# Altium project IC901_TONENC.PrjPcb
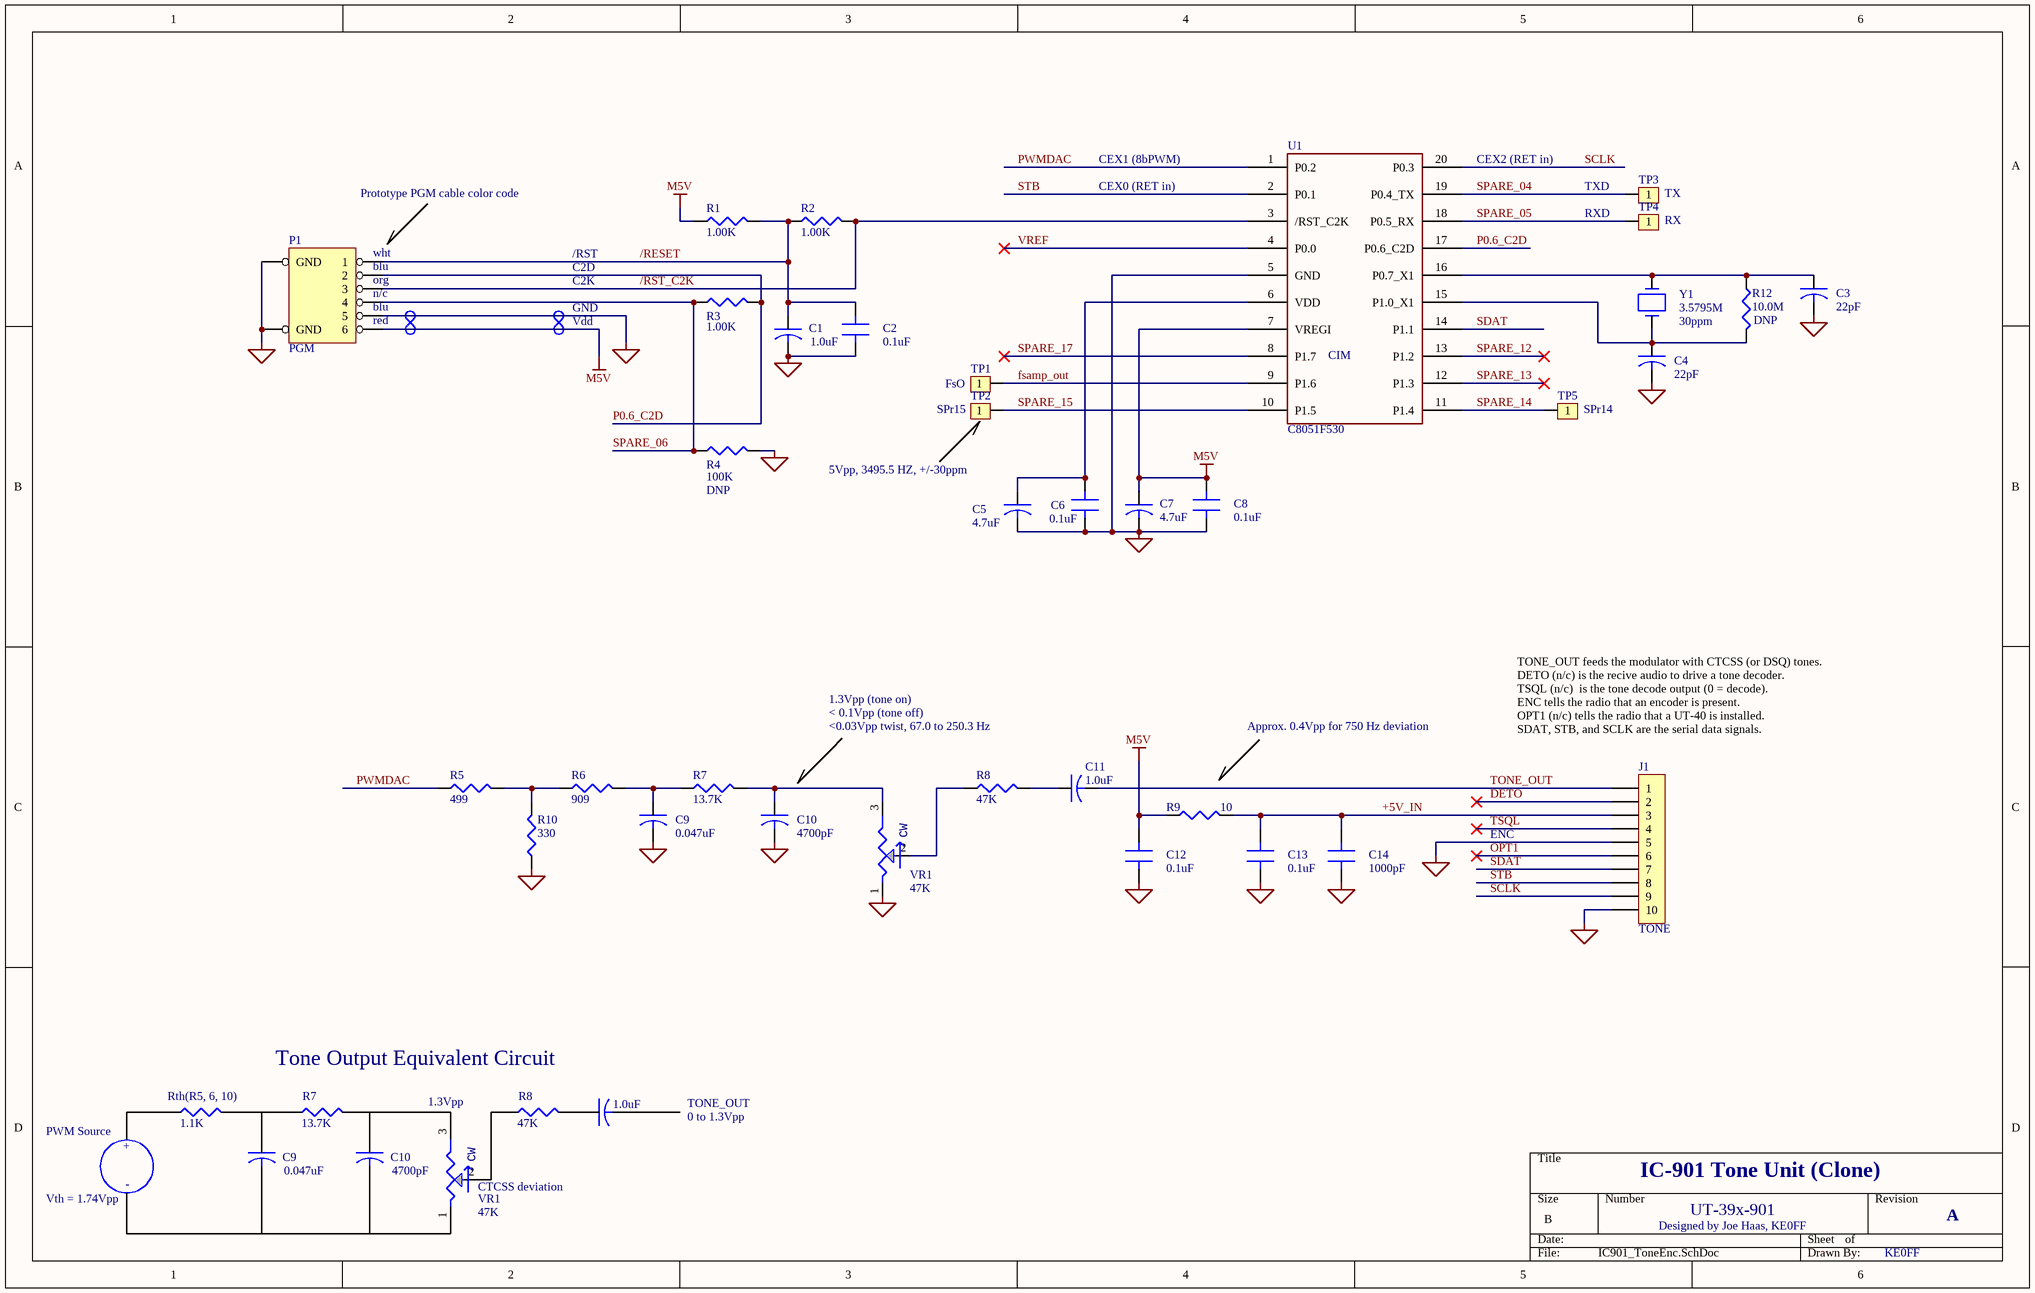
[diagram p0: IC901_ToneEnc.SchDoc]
1 sheet, 42 parts. Net scope: global (net labels, ports and power ports of the same name join across sheets).
Board file: IC901_ToneEnc.PcbDoc

## Sheet IC901_ToneEnc.SchDoc
size B; SheetNumber: 1; SheetTotal: 1

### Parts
C1  1.0uF  [0805]
C2  0.1uF  [0402]
C3  22pF  [0402]
C4  22pF  [0402]
C5  4.7uF  [0805]
C6  0.1uF  [0402]
C7  4.7uF  [0805]
C8  0.1uF  [0402]
C9  0.047uF  [1206]
C10  4700pF  [0805]
C11  1.0uF  [0805]
C12  0.1uF  [0402]
C13  0.1uF  [0402]
C14  1000pF  [0402]
Ce1  0.047uF  [1206]
Ce2  4700pF  [0805]
Ce3  1.0uF  [0805]  (graphical)
J1  TONE  [MOLEX_1.5mm_SMD_10POS]
P1  PGM  [CON_1.25MM_6P]
R1  1.00K  [0402]
R2  1.00K  [0402]
R3  1.00K  [0402]
R4  100K  [0402]
R5  499  [0402]
R6  909  [0402]
R7  13.7K  [0402]
R8  47K  [0402]
R9  10  [1206]
R10  330  [0402]
R12  10.0M  [0402]
Re1  1.1K  [0402]  (graphical)
Re2  13.7K  [0402]  (graphical)
Re3  47K  [0402]  (graphical)
TP1  FsO  [TP-SMD-20x50-SQ]  (no BOM)
TP2  SPr15  [TP-SMD-20x50-SQ]  (no BOM)
TP3  TX  [TP-SMD-20x50-SQ]  (no BOM)
TP4  RX  [TP-SMD-20x50-SQ]  (no BOM)
TP5  SPr14  [TP-SMD-20x50-SQ]  (no BOM)
U1  C8051F530  [TSSOP-20]
VR1  47K  [POT_3313]
VRe1  47K  [POT_3313]  (graphical)
Y1  3.5795M  Stability: 30ppm  [XTAL_AT49_SMD]

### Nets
GND: C1.2 C2.2 C3.2 C4.2 C5.2 C6.2 C7.2 C8.2 C9.2 C10.2 C12.2 C13.2 C14.2 J1.5 J1.10 P1.5 P1.7(GND) P1.8(GND) R4.1 R10.2 U1.5(GND) VR1.1(A)
M5V: C7.1 C8.1 C12.1 P1.6 R1.2 R9.2 U1.7(VREGI)
+5V_IN: C13.1 C14.1 J1.3 R9.1
/RESET: C1.1 C2.1 P1.1 R1.1 R2.2
/RST_C2K: P1.3 R2.1 U1.3(/RST_C2K)
DETO: J1.2
fsamp_out: TP1.1 U1.9(P1.6)
OPT1: J1.6
P0.6_C2D: P1.2 R3.1 U1.17(P0.6_C2D)
PWMDAC: R5.2 U1.1(P0.2)
SCLK: J1.9 U1.20(P0.3)
SDAT: J1.7 U1.14(P1.1)
SPARE_04: TP3.1 U1.19(P0.4_TX)
SPARE_05: TP4.1 U1.18(P0.5_RX)
SPARE_06: P1.4 R3.2 R4.2
SPARE_12: U1.13(P1.2)
SPARE_13: U1.12(P1.3)
SPARE_14: TP5.1 U1.11(P1.4)
SPARE_15: TP2.1 U1.10(P1.5)
SPARE_17: U1.8(P1.7)
STB: J1.8 U1.2(P0.1)
TONE_OUT: C11.2 J1.1
TSQL: J1.4
VREF: U1.4(P0.0)
NetC3_1: C3.1 R12.1 U1.16(P0.7_X1) Y1.2
NetC4_1: C4.1 R12.2 U1.15(P1.0_X1) Y1.1
NetC5_1: C5.1 C6.1 U1.6(VDD)
NetC9_1: C9.1 R6.1 R7.2
NetC10_1: C10.1 R7.1 VR1.3(B)
NetC11_1: C11.1 R8.1
NetR5_1: R5.1 R6.2 R10.1
NetR8_2: R8.2 VR1.2(WIPER)

Not connected (* = marked no-connect by the designer): Ce1 1 2; Ce2 1 2; Ce3 1 2; Re1 1 2; Re2 1 2; Re3 1 2; VRe1 1(A) 2(WIPER) 3(B)

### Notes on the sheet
- CEX1 (8bPWM)
- CEX2 (RET in)
- Prototype PGM cable color code
- CEX0 (RET in)
- TXD
- RXD
- (near P1) wht
- (near P1) blu
- (near P1) org
- (near P1) n/c
- /RST
- C2D
- C2K
- (near P1) red
- GND
- Vdd
- (near U1) CIM
- 5Vpp, 3495.5 HZ, +/-30ppm
- 1.3Vpp (tone on)
- < 0.1Vpp (tone off)
- <0.03Vpp twist, 67.0 to 250.3 Hz
- Approx. 0.4Vpp for 750 Hz deviation
- (near J1) TONE_OUT feeds the modulator with CTCSS (or DSQ) tones.
  DETO (n/c) is the recive audio to drive a tone decoder.
  TSQL (n/c)  is the tone decode output (0 = decode).
  ENC tells the radio that an encoder is present.
  OPT1 (n/c) tells the radio that a UT-40 is installed.
  SDAT, STB, and SCLK are the serial data signals.
- ENC
- (near Re1) Rth(R5, 6, 10)
- Tone Output Equivalent Circuit
- (near Re2) R7
- (near VRe1) 1.3Vpp
- (near Re3) R8
- TONE_OUT
- PWM Source
- +
- (near Ce1) C9
- (near Ce2) C10
- 0 to 1.3Vpp
- IC-901 Tone Unit (Clone)
- Vth = 1.74Vpp
- -
- (near VRe1) VR1
- (near VRe1) CTCSS deviation
- UT-39x-901
- Designed by Joe Haas, KE0FF
- A
- KE0FF

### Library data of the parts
C1 C11 Ce3 = CAP 0805: CAP, CER, 0805, 1.0uF, 25V; MPN: CL21B105KBFNNNF; MFR: Samsung
C2 C6 C8 C12 C13 = CAP CER: CAP, CER, 0402, 0.1uF, 50V; MPN: 04025C104KAT2A; MFR: AVX
C3 C4 = CAP 0805: CAP, MLCC, NPO, 1%, 0402, 50V, 22pF; MPN: GCM1555C1H220FA16D; MFR: Murata; VOLTAGE: 50
C5 C7 = CAP 0805: CAP, CER, 0805, 4.7uF, 10V; MPN: C2012X7R1A475K125AC; MFR: TDK
C9 Ce1 = CAP 0805: CAP, CER, NPO, 0805, 50V, 47nF; MPN: CC1206JKNPO9BN473; MFR: Yageo
C10 Ce2 = CAP 0805: CAP, CER, 0805, NPO, 50V, 4700pF; MPN: 0805N472J500CT; MFR: Walsin
C14 = CAP CER: CAP, CER, 0402, 50V, 1000pF; MPN: CC0402JRNPO9BN102; MFR: Yageo
J1 = CON10: CON, 10POS, 1.5mm, RTANG, SMD; MPN: 87438-1043; MFR: Molex
P1 = HEADER-6-PIN-RT-ANG: CON, 6POS, 1.25MM, SMD; MPN: 53398-0671; MFR: Molex; ALTPN: 53398-0671 (V), or 53261-0671 (RA)
R1-R3 = R0805: RES, CHP, 0402, 1%, 1K; MPN: RC0402FR-071KL; MFR: Yageo
R4 = R0805: RES, CHP, 0402, 1%, 100K; MPN: RC0402FR-07100KL; MFR: Yageo
R5 = R0805: RES, CHP, 0402, 1%, 499; MPN: RC0402FR-07499RL; MFR: Yageo
R6 Re1-Re3 = R0805: RES, CHP, 0402, 1%, 909; MPN: RC0402FR-07909RL; MFR: Yageo
R7 = R0805: RES, CHP, 0402, 1%, 13.7K; MPN: RC0402FR-0713K7L; MFR: Yageo
R8 = R0805: RES, CHP, 0402, 1%, 47K; MPN: RC0402FR-0747KL; MFR: Yageo
R9 = R0805: RES, CHP, 0402, 1%, 10.0; MPN: RC1206FR-7W10RL; MFR: Yageo
R10 = R0805: RES, CHP, 0402, 1%, 330; MPN: RC0402FR-07330RL; MFR: Yageo
R12 = R0805: RES, CHP, 0402, 1%, 10.0M; MPN: RC0402FR-0710ML; MFR: Yageo
TP1-TP5 = TP
U1 = C8051F531: IC, MCU, 8051, F531; MPN: C8051F531-C-IT; MFR: SiLabs
VR1 = RESISTOR VAR: RES, VAR, MICRO, SMD, 1T, 47K; MPN: 3313X-1-503E; MFR: Bourns
VRe1 = RESISTOR VAR: MPN: 3313X-1-503E; MFR: Bourns
Y1 = CRYSTAL-2PIN: CRSTL, QRTZ, HC49U, <=50ppm; MPN: ABLSG-3.579545MHZ-D2Y-T; MFR: Abracon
